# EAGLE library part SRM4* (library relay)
Safety Relay SCHRACK 4 pole 8 A Source: http://www.schrack.com/.. 6685.pdf
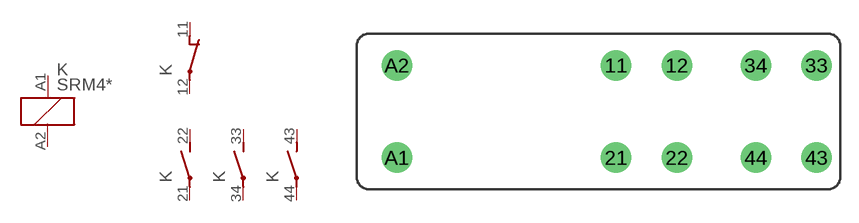
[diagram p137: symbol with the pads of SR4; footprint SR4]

Designator prefix K; gates 1=K 2=O 3=S 4=S 5=S

## SRM4005 (OC_FARNELL: unknown; OC_NEWARK: unknown), SRM4006 (OC_FARNELL: unknown; OC_NEWARK: unknown), SRM4009 (OC_FARNELL: unknown; OC_NEWARK: unknown), SRM4012 (OC_FARNELL: unknown; OC_NEWARK: unknown), SRM4015 (OC_FARNELL: unknown; OC_NEWARK: unknown), SRM4018 (OC_FARNELL: unknown; OC_NEWARK: unknown), SRM4021 (OC_FARNELL: unknown; OC_NEWARK: unknown), SRM4024 (OC_FARNELL: unknown; OC_NEWARK: unknown), SRM4036 (OC_FARNELL: unknown; OC_NEWARK: unknown), SRM4040 (OC_FARNELL: unknown; OC_NEWARK: unknown), SRM4048 (OC_FARNELL: unknown; OC_NEWARK: unknown), SRM4060 (OC_FARNELL: unknown; OC_NEWARK: unknown), SRM4085 (OC_FARNELL: unknown; OC_NEWARK: unknown), SRM4110 (OC_FARNELL: unknown; OC_NEWARK: unknown)  [SR4]
11  2:O  pas
12  2:P  pas
21  3:P  pas
22  3:S  pas
33  4:S  pas
34  4:P  pas
43  5:S  pas
44  5:P  pas
A1  1:1  pas
A2  1:2  pas

## Footprint SR4 (pad centres in mm)
Safety Relay SCHRACK 4 pole 8 A Source: http://www.schrack.com/.. 6685.pdf
drill 1.3 pad 2.5 round: 11 0,3.8; 12 5,3.8; 21 0,-3.8; 22 5,-3.8; 33 16.5,3.8; 34 11.5,3.8; 43 16.5,-3.8; 44 11.5,-3.8; A1 -18.05,-3.8; A2 -18.05,3.8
